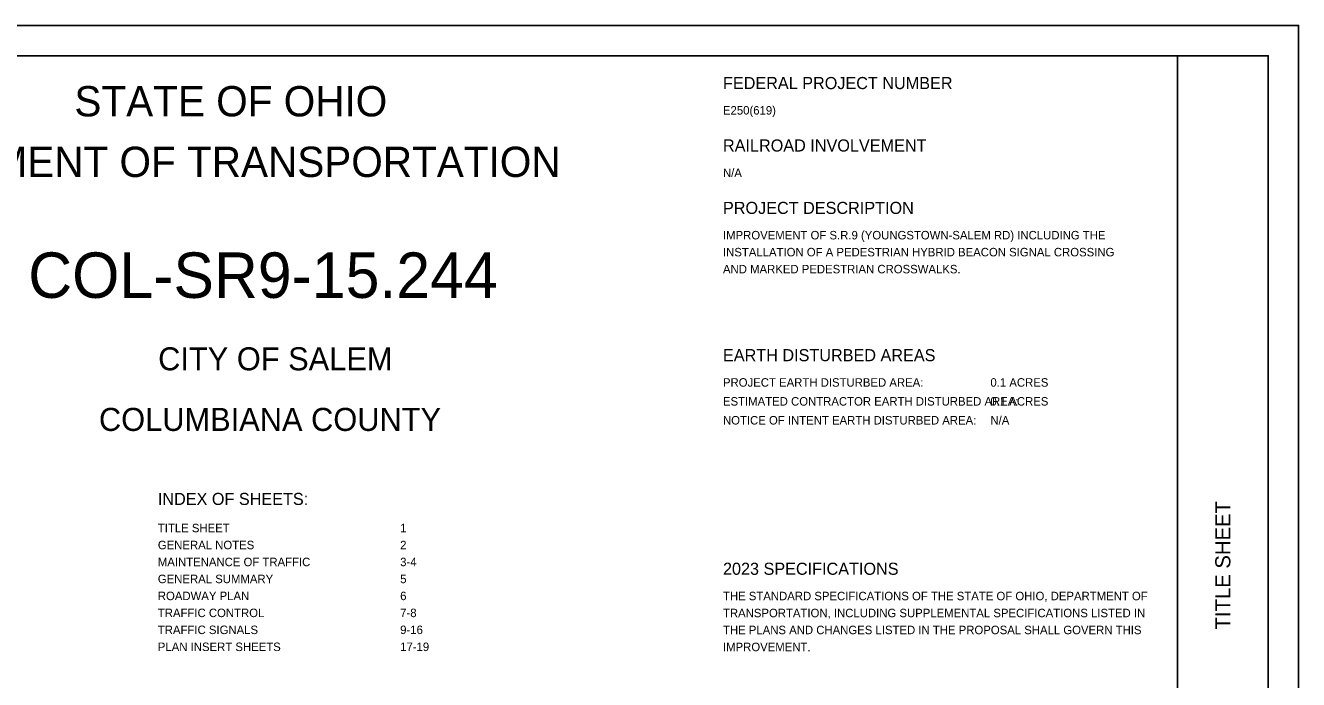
# Model space of a CAD drawing. Extents: x 0 to 34, y 0 to 22.
# Drawn here: x 12.99 to 34, y 11.21 to 22 of the extents above; entities that cross this region are included whole.
import ezdxf

# ---------------------------------------------------------------- set-up
doc = ezdxf.new("R2010")
doc.units = 0
for name, color, linetype in [('SH_Border', 7, 'Continuous'), ('SH_Cut_Line', 7, 'Continuous'), ('SH_Data', 7, 'Continuous'), ('SH_Text', 7, 'Continuous')]:
    doc.layers.add(name, color=color, linetype=linetype)

msp = doc.modelspace()

# ---------------------------------------------------------------- linework, layer by layer
at = {"layer": 'SH_Border'}
msp.add_line((32, 0.5), (32, 21.5), dxfattribs=at)
msp.add_lwpolyline([(1.5, 21.5), (33.5, 21.5), (33.5, 0.5), (1.5, 0.5)], close=True, dxfattribs=at)
at = {"layer": 'SH_Cut_Line'}
msp.add_lwpolyline([(0, 0), (34, 0), (34, 22), (0, 22)], close=True, dxfattribs=at)

# ---------------------------------------------------------------- texts
at = {"layer": 'SH_Data'}
msp.add_text('TITLE SHEET', height=0.25, rotation=90, dxfattribs=at).set_placement((32.875, 12.035))
at = {"layer": 'SH_Text'}
for s, height, p in [('FEDERAL PROJECT NUMBER', 0.2, (24.5, 20.95)), ('STATE OF OHIO', 0.5, (13.795, 20.5)), ('E250(619)', 0.14, (24.5, 20.53)), ('DEPARTMENT OF TRANSPORTATION', 0.5, (9.747, 19.5)), ('RAILROAD INVOLVEMENT', 0.2, (24.5, 19.92)), ('N/A', 0.14, (24.5, 19.5)), ('PROJECT DESCRIPTION', 0.2, (24.5, 18.89)), ('IMPROVEMENT OF S.R.9 (YOUNGSTOWN-SALEM RD) INCLUDING THE ', 0.14, (24.5, 18.47)), ('INSTALLATION OF A PEDESTRIAN HYBRID BEACON SIGNAL CROSSING', 0.14, (24.5, 18.19)), ('COL-SR9-15.244', 0.75, (13.033, 17.505)), ('AND MARKED PEDESTRIAN CROSSWALKS.', 0.14, (24.5, 17.91)), ('CITY OF SALEM', 0.38, (15.177, 16.31)), ('EARTH DISTURBED AREAS', 0.2, (24.5, 16.46)), ('PROJECT EARTH DISTURBED AREA:', 0.14, (24.5, 16.04)), ('0.1 ACRES', 0.14, (28.914, 16.04)), ('ESTIMATED CONTRACTOR EARTH DISTURBED AREA:', 0.14, (24.5, 15.728)), ('0.1 ACRES', 0.14, (28.914, 15.728)), ('COLUMBIANA COUNTY', 0.38, (14.2, 15.31)), ('NOTICE OF INTENT EARTH DISTURBED AREA:', 0.14, (24.5, 15.416)), ('N/A', 0.14, (28.914, 15.416)), ('INDEX OF SHEETS:', 0.2, (15.172, 14.088)), ('TITLE SHEET', 0.14, (15.172, 13.638)), ('1', 0.14, (19.172, 13.638)), ('GENERAL NOTES', 0.14, (15.172, 13.358)), ('2', 0.14, (19.172, 13.358)), ('MAINTENANCE OF TRAFFIC', 0.14, (15.172, 13.078)), ('3-4', 0.14, (19.172, 13.078)), ('2023 SPECIFICATIONS', 0.2, (24.5, 12.936)), ('GENERAL SUMMARY', 0.14, (15.172, 12.798)), ('5', 0.14, (19.172, 12.798)), ('ROADWAY PLAN', 0.14, (15.172, 12.518)), ('6', 0.14, (19.172, 12.518)), ('THE STANDARD SPECIFICATIONS OF THE STATE OF OHIO, DEPARTMENT OF ', 0.14, (24.5, 12.516)), ('TRAFFIC CONTROL', 0.14, (15.172, 12.238)), ('7-8', 0.14, (19.172, 12.238)), ('TRANSPORTATION, INCLUDING SUPPLEMENTAL SPECIFICATIONS LISTED IN ', 0.14, (24.5, 12.236)), ('TRAFFIC SIGNALS', 0.14, (15.172, 11.958)), ('9-16', 0.14, (19.172, 11.958)), ('THE PLANS AND CHANGES LISTED IN THE PROPOSAL SHALL GOVERN THIS ', 0.14, (24.5, 11.956)), ('PLAN INSERT SHEETS', 0.14, (15.172, 11.678)), ('17-19', 0.14, (19.172, 11.678)), ('IMPROVEMENT.', 0.14, (24.5, 11.676))]:
    msp.add_text(s, height=height, dxfattribs=at).set_placement(p)

doc.saveas('drawing.dxf')
